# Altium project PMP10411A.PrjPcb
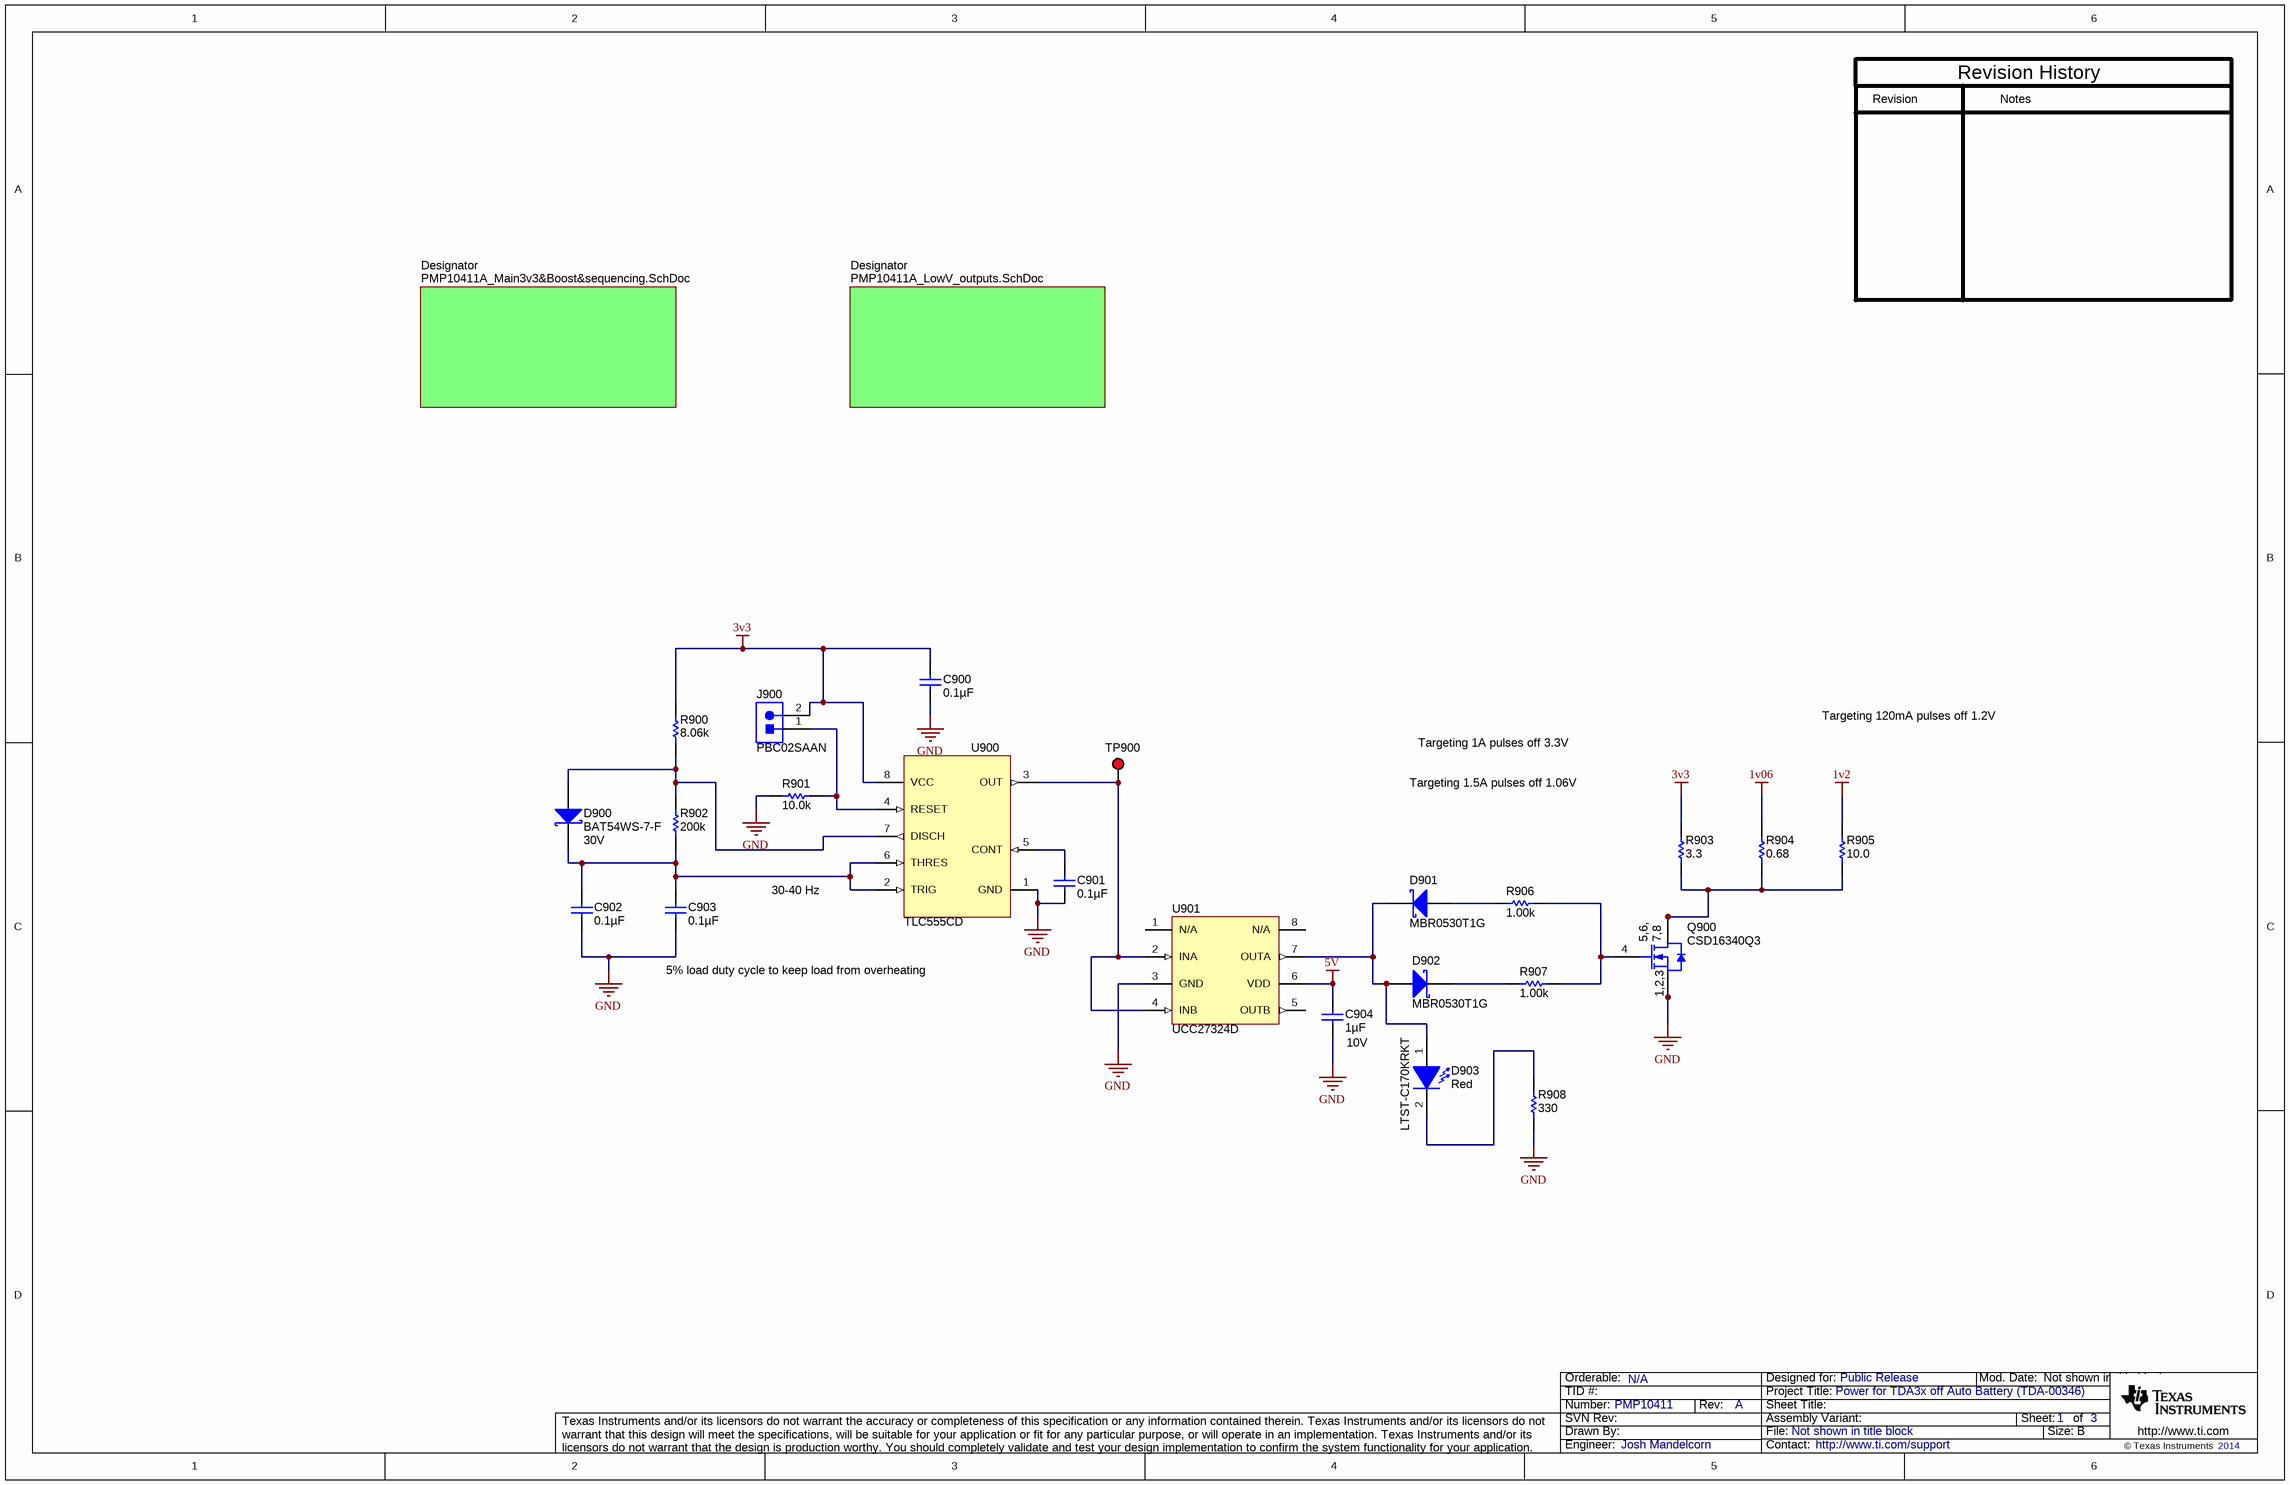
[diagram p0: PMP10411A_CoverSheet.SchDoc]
TechSupport: http://www.ti.com/support; SCH_Rev: A; PRJ_Title: Power for TDA3x off Auto Battery (TDA-00346); PRJ_Number: PMP10411; PRJ_Engineer: Josh Mandelcorn; PRJ_Customer: Public Release; PCB_Rev: A; PCB_Layout: Who did the Layout?; EVM_Orderable: N/A; CopyrightYear: 2014
3 sheets, 168 parts. Net scope: flat (ports and power ports of the same name join across sheets).
Board file: PMP10411A_TID.PcbDoc
Sheets:
  PMP10411A_CoverSheet.SchDoc
    Designator = PMP10411A_Main3v3&Boost&sequencing.SchDoc
    Designator = PMP10411A_LowV_outputs.SchDoc

## Sheet PMP10411A_CoverSheet.SchDoc
size 431 x 279 mm; Date: Not shown in title block; ApprovedBy: Not shown in title block; CheckedBy: Not shown in title block; Author: Not shown in title block; CompanyName: Not shown in title block; Engineer: Not shown in title block; Organization: Not shown in title block; Address1: Not shown in title block; Address2: Not shown in title block; Address3: Not shown in title block; Address4: Not shown in title block; DocumentNumber: 1; Revision: Use project parameter SCH_Rev; SheetNumber: 1; SheetTotal: 3; PageSetup: Record=PageOptions¦CenterHorizontal=True¦CenterVertical=True¦PrintScale=1.00¦XCorrection=1.00¦YCorrection=1.00¦PrintKind=0¦BorderSize=5000000¦LeftOffset=0¦BottomOffset=0¦Orientation=2¦PaperLength=1000¦PaperWidth=1000¦Scale=100¦PaperSource=15¦PrintQuality=600¦MediaType=1¦DitherType=10¦PaperKind=Letter¦PrintScaleMode=1

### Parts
C900  ValueDisplayed: 0.1µF  [0402]  (hidden comment: C1005X7R1H104M)
C901  ValueDisplayed: 0.1µF  [0402]  (hidden comment: C1005X7R1H104M)
C902  ValueDisplayed: 0.1µF  [0402]  (hidden comment: C1005X7R1H104M)
C903  ValueDisplayed: 0.1µF  [0402]  (hidden comment: C1005X7R1H104M)
C904  ValueDisplayed: 1µF  Value2: 10V  [0402]  (hidden comment: GRM155R61A105KE15D)
D900  BAT54WS-7-F  value 30V  [sod-323]
D901  MBR0530T1G  [SOD-123]
D902  MBR0530T1G  [SOD-123]
D903  LTST-C170KRKT  value Red  [LED_LTST-C170]
J900  PBC02SAAN  [Sullins_PBC02SAAN]
Q900  CSD16340Q3  [TRANS_NexFET_Q3]
R900  value 8.06k  [0402]  (hidden comment: CRCW04028K06FKED)
R901  value 10.0k  [0402]  (hidden comment: CRCW040210K0FKED)
R902  value 200k  [0402]  (hidden comment: CRCW0402200KFKED)
R903  ValueDisplayed: 3.3  [1210M]  (hidden comment: ERJ-P14J3R3U)
R904  ValueDisplayed: 0.68  [1206]  (hidden comment: ERJ-8RQFR68V)
R905  ValueDisplayed: 10.0  [1206]  (hidden comment: CRCW120610R0FKEA)
R906  ValueDisplayed: 1.00k  [0603]  (hidden comment: CRCW06031K00FKEA)
R907  ValueDisplayed: 1.00k  [0603]  (hidden comment: CRCW06031K00FKEA)
R908  value 330  [0402]  (hidden comment: CRCW0402330RJNED)
TP900  5000  [Keystone5000]  (value not drawn)
U900  TLC555CD  [D0008A_N]
U901  UCC27324D  [D0008A_N]

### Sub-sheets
Designator = PMP10411A_Main3v3&Boost&sequencing.SchDoc: no entries
Designator = PMP10411A_LowV_outputs.SchDoc: no entries

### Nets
1v2: R905.2
1v06: R904.2
3v3: C900.1 J900.2 R900.2 R903.2 U900.8(VCC)
5V: C904.1 U901.6(VDD)
GND: C900.2 C901.2 C902.2 C903.2 C904.2 Q900.1(S) Q900.2(S) Q900.3(S) R901.1 R908.1 U900.1(GND) U901.3(GND)
NetC901_1: C901.1 U900.5(CONT)
NetC902_1: C902.1 C903.1 D900.1(K) R902.1 U900.2(TRIG) U900.6(THRES)
NetD900_2: D900.2(A) R900.1 R902.2 U900.7(DISCH)
NetD901_1: D901.1(K) D902.2(A) D903.1(A) U901.7(OUTA)
NetD901_2: D901.2(A) R906.1
NetD902_1: D902.1(K) R907.1
NetD903_2: D903.2(K) R908.2
NetJ900_1: J900.1 R901.2 U900.4(RESET)
NetQ900_4: Q900.4(G) R906.2 R907.2
NetQ900_5: Q900.5(D) Q900.6(D) Q900.7(D) Q900.8(D) R903.1 R904.1 R905.1
NetTP900_1: TP900.1 U900.3(OUT) U901.2(INA) U901.4(INB)

Not connected (* = marked no-connect by the designer): U901 1(N/A) 5(OUTB) 8(N/A)

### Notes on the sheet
- Revision
- Notes
- Revision History
- Targeting 1A pulses off 3.3V
- Targeting 120mA pulses off 1.2V
- Targeting 1.5A pulses off 1.06V
- 30-40 Hz
- 5% load duty cycle to keep load from overheating

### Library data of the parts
C900-C903 = C1005X7R1H104M: CAP, CERM, 0.1uF, 50V, +/-20%, X7R, 0402; Manufacturer: TDK; Polarized: N; CompType: Capacitor; U/M: EA; Cap_F: 0.0000001; Tolerance_%: 20; Value1: Unknown; VDC_V: 50; TempCo: C0G/NP0; TaMin_C: -55; TaMax_C: 125
C904 = GRM155R61A105KE15D: CAP, CERM, 1uF, 10V, +/-10%, X5R, 0402; Manufacturer: MuRata; Polarized: N; CompType: Capacitor; U/M: EA; Cap_F: 0.000001; Tolerance_%: 10; Value1: Unknown; TaMin_C: -55; TaMax_C: 85
D900 = BAT54WS-7-F: Diode, Schottky, 30V, 0.2A, SOD-323; Manufacturer: Diodes Inc.; U/M: EA; Vf_V: 0.7; Value2: 0.7V; Io_A: 0.2; Vr_V: 30; TJmax_C: 125
D901 D902 = MBR0530T1G: Diode, Schottky, 30V, 0.5A, SOD-123; Manufacturer: ON Semiconductor; U/M: EA; Vf_V: 0.43; Value2: 0.43V; Io_A: 0.5; Vr_V: 30; TJmax_C: 125; RJC_CperW: 150
D903 = LTST-C170KRKT: LED, Red, SMD; Manufacturer: Lite-On; Type: AlInGaP; Vf_V: 2; Value2: 2V; Io_A: 20; Value1: W; U/M: EA
J900 = PBC02SAAN: Header, 100mil, 2x1, Gold, TH; Manufacturer: Sullins Connector Solutions; SymbolCreator: a0412235; U/M: EA
Q900 = CSD16340Q3: MOSFET, N-CH, 25 V, 60 A, SON 3.3x3.3mm; Manufacturer: Texas Instruments; Alternate Manufacturer: None; U/M: EA; ChType: N; Value: 25V; VdsMax_V: 25; Value1: 0.0043 ohm; Rdson45_ohm: 0.0043; Value2: 6.5 nC; QgTyp_nC: 6.5; Vgs_V: 10; IdsMax_A: 60
R900 = CRCW04028K06FKED: RES, 8.06k ohm, 1%, 0.063W, 0402; Manufacturer: Vishay-Dale; CompType: Resistor; Res_ohm: 8060; Value_Code: 8k06; Tolerance_%: 1; Power_W: 0.063; VDC_V: 50; TempCo: 100 ppm/C; EIA_Code: E96; U/M: EA
R901 = CRCW040210K0FKED: RES, 10.0k ohm, 1%, 0.063W, 0402; Manufacturer: Vishay-Dale; CompType: Resistor; Res_ohm: 10000; Value_Code: 10k0; Tolerance_%: 1; Power_W: 0.063; VDC_V: 50; TempCo: 100 ppm/C; EIA_Code: E96; U/M: EA
R902 = CRCW0402200KFKED: RES, 200k ohm, 1%, 0.063W, 0402; Manufacturer: Vishay-Dale; CompType: Resistor; Res_ohm: 200000; Tolerance_%: 1; Power_W: 0.063; VDC_V: 50; TempCo: 100 ppm/C; EIA_Code: E96; U/M: EA
R903 = ERJ-P14J3R3U: RES, 3.3, 5%, 0.5 W, 1210; Manufacturer: Panasonic; CompType: Resistor; Value: 3.3; Value_Code: 3R30; Tolerance_%: 5; Power_W: 0.5; Value2: 0.5W; VDC_V: 200; TempCo: 600 ppm/C; EIA_Code: E24; U/M: EA
R904 = ERJ-8RQFR68V: RES, 0.68, 1%, 0.25 W, 1206; Manufacturer: Panasonic; CompType: Resistor; Value: 0.68; Value_Code: R680; Tolerance_%: 1; Power_W: 0.25; Value2: 0.25W; TempCo: 250 ppm/C; EIA_Code: E96; U/M: EA
R905 = CRCW120610R0FKEA: RES, 10.0, 1%, 0.25 W, 1206; Manufacturer: Vishay-Dale; CompType: Resistor; Value: 10.0; Res_ohm: 10; Value_Code: 10R0; Tolerance_%: 1; Power_W: 0.25; Value2: 0.25W; VDC_V: 200; TempCo: 100 ppm/C; EIA_Code: E96; U/M: EA
R906 R907 = CRCW06031K00FKEA: RES, 1.00 k, 1%, 0.1 W, 0603; Manufacturer: Vishay-Dale; CompType: Resistor; Value: 1.00k; Res_ohm: 1000; Value_Code: 1k00; Tolerance_%: 1; Power_W: 0.1; Value2: 0.1W; VDC_V: 75; TempCo: 100 ppm/C; EIA_Code: E96; U/M: EA
R908 = CRCW0402330RJNED: RES, 330 ohm, 5%, 0.063W, 0402; Manufacturer: Vishay-Dale; CompType: Resistor; Value_Code: 330R; Tolerance_%: 5; Power_W: 0.063; VDC_V: 50; TempCo: 200 ppm/C; EIA_Code: E24; U/M: EA
TP900 = 5000: Test Point, Miniature, Red, TH; Manufacturer: Keystone; CompType: Test Point Loop; U/M: EA
U900 = TLC555CD: LinCMOS Timer, D0008A; Manufacturer: Texas Instruments; SymbolCreator: a0799628; CompType: IC; U/M: EA
U901 = UCC27324D: DUAL 4-A PEAK HIGH SPEED LOW- SIDE POWER MOSFET DRIVERS, D0008A; Manufacturer: Texas Instruments; SymbolCreator: a0412235; CompType: IC; U/M: EA

## Sheet PMP10411A_Main3v3&Boost&sequencing.SchDoc
size 431 x 279 mm; Date: Not shown in title block; ApprovedBy: Not shown in title block; CheckedBy: Not shown in title block; Author: Not shown in title block; CompanyName: Not shown in title block; Engineer: Not shown in title block; Organization: Not shown in title block; Address1: Not shown in title block; Address2: Not shown in title block; Address3: Not shown in title block; Address4: Not shown in title block; DocumentNumber: 2; Revision: Use project parameter SCH_Rev; SheetNumber: 2; SheetTotal: 3; PageSetup: Record=PageOptions¦CenterHorizontal=True¦CenterVertical=True¦PrintScale=1.00¦XCorrection=1.00¦YCorrection=1.00¦PrintKind=0¦BorderSize=5000000¦LeftOffset=0¦BottomOffset=0¦Orientation=2¦PaperLength=1000¦PaperWidth=1000¦Scale=100¦PaperSource=15¦PrintQuality=600¦MediaType=1¦DitherType=10¦PaperKind=Letter¦PrintScaleMode=1
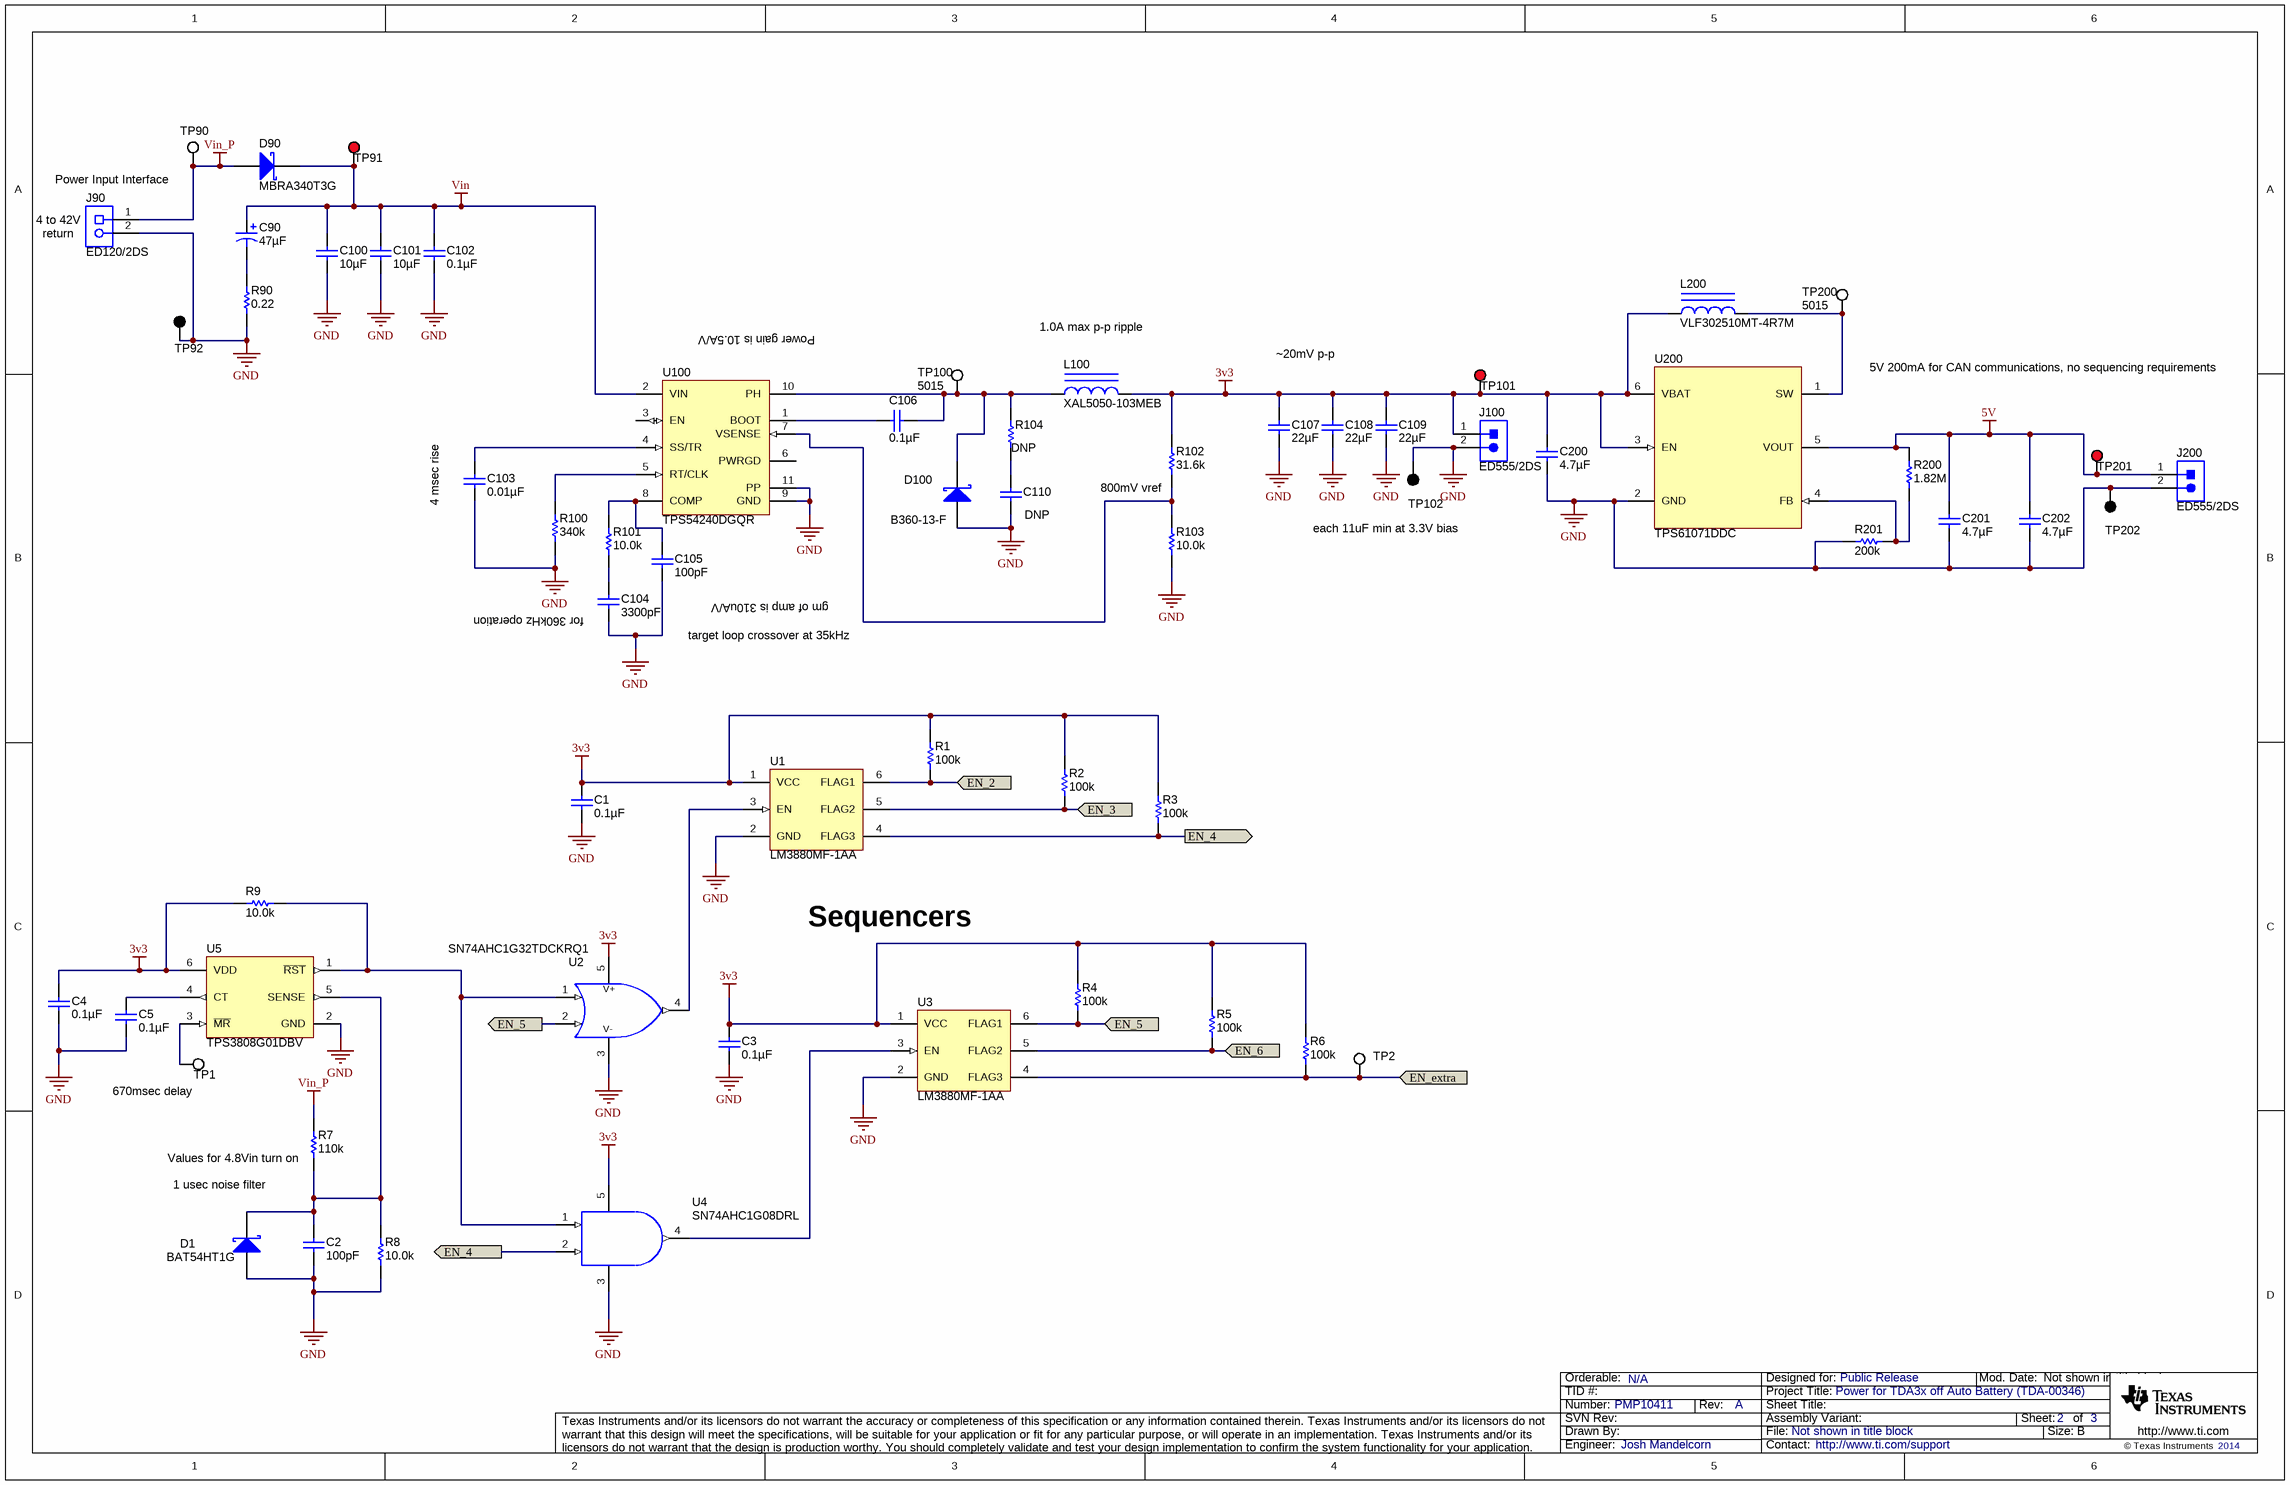
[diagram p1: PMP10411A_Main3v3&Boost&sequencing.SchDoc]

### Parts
C1  ValueDisplayed: 0.1µF  [0402]  (hidden comment: GRM155R61E104KA87D)
C2  ValueDisplayed: 100pF  [0402]  (hidden comment: GRM1535C1H101JDD5D)
C3  ValueDisplayed: 0.1µF  [0402]  (hidden comment: GRM155R61E104KA87D)
C4  ValueDisplayed: 0.1µF  [0402]  (hidden comment: GRM155R61E104KA87D)
C5  ValueDisplayed: 0.1µF  [0402]  (hidden comment: GRM155R61E104KA87D)
C90  ValueDisplayed: 47µF  [SM_RADIAL_6.3BMM]  (hidden comment: UUD1H470MCL1GS)
C100  ValueDisplayed: 10µF  [1210]  (hidden comment: GRM32ER71H106KA12L)
C101  ValueDisplayed: 10µF  [1210]  (hidden comment: GRM32ER71H106KA12L)
C102  ValueDisplayed: 0.1µF  [0603]  (hidden comment: 06035C104KAT2A)
C103  ValueDisplayed: 0.01µF  [0402]  (hidden comment: C1005X7R1E103K)
C104  ValueDisplayed: 3300pF  [0402]  (hidden comment: C1005X7R1H332K)
C105  ValueDisplayed: 100pF  [0402]  (hidden comment: GRM1535C1H101JDD5D)
C106  ValueDisplayed: 0.1µF  [0402]  (hidden comment: GRM155R61E104KA87D)
C107  ValueDisplayed: 22µF  [0805_HV]  (hidden comment: GRM21BR61A226ME44)
C108  ValueDisplayed: 22µF  [0805_HV]  (hidden comment: GRM21BR61A226ME44)
C109  ValueDisplayed: 22µF  [0805_HV]  (hidden comment: GRM21BR61A226ME44)
C110  DNP  [0603]  (value not drawn)
C200  ValueDisplayed: 4.7µF  [0603]  (hidden comment: CGB3B1X5R1A475K055AC)
C201  ValueDisplayed: 4.7µF  [0603]  (hidden comment: CGB3B1X5R1A475K055AC)
C202  ValueDisplayed: 4.7µF  [0603]  (hidden comment: CGB3B1X5R1A475K055AC)
D1  BAT54HT1G  [sod-323]
D90  MBRA340T3G  [SMA]
D100  B360-13-F  [SMC]
J90  ED120/2DS  [CONN_ED120-2DS]
J100  ED555/2DS  [TERM_BLK_ED555-2DS]
J200  ED555/2DS  [TERM_BLK_ED555-2DS]
L100  XAL5050-103MEB  [XAL5050]
L200  VLF302510MT-4R7M  [VLF302510]
R1  ValueDisplayed: 100k  [0402]  (hidden comment: CRCW0402100KFKED)
R2  ValueDisplayed: 100k  [0402]  (hidden comment: CRCW0402100KFKED)
R3  ValueDisplayed: 100k  [0402]  (hidden comment: CRCW0402100KFKED)
R4  ValueDisplayed: 100k  [0402]  (hidden comment: CRCW0402100KFKED)
R5  ValueDisplayed: 100k  [0402]  (hidden comment: CRCW0402100KFKED)
R6  ValueDisplayed: 100k  [0402]  (hidden comment: CRCW0402100KFKED)
R7  ValueDisplayed: 110k  [0402]  (hidden comment: CRCW0402110KFKED)
R8  ValueDisplayed: 10.0k  [0402]  (hidden comment: CRCW040210K0FKED)
R9  ValueDisplayed: 10.0k  [0402]  (hidden comment: CRCW040210K0FKED)
R90  ValueDisplayed: 0.22  [0603]  (hidden comment: ERJ-3RQFR22V)
R100  ValueDisplayed: 340k  [0402]  (hidden comment: CRCW0402340KFKED)
R101  ValueDisplayed: 10.0k  [0402]  (hidden comment: CRCW040210K0FKED)
R102  ValueDisplayed: 31.6k  [0402]  (hidden comment: CRCW040231K6FKED)
R103  ValueDisplayed: 10.0k  [0402]  (hidden comment: CRCW040210K0FKED)
R104  DNP  [0805_HV]  (value not drawn)
R200  ValueDisplayed: 1.82M  [0402]  (hidden comment: CRCW04021M82FKED)
R201  ValueDisplayed: 200k  [0402]  (hidden comment: CRCW0402200KFKED)
TP1  5002  [Keystone5002]  (value not drawn)
TP2  5002  [Keystone5002]  (value not drawn)
TP90  5002  [Keystone5002]  (value not drawn)
TP91  5000  [Keystone5000]  (value not drawn)
TP92  5001  [Keystone5001]  (value not drawn)
TP100  5015  [Testpoint_Keystone_Miniature]
TP101  5000  [Keystone5000]  (value not drawn)
TP102  5001  [Keystone5001]  (value not drawn)
TP200  5015  [Testpoint_Keystone_Miniature]
TP201  5000  [Keystone5000]  (value not drawn)
TP202  5001  [Keystone5001]  (value not drawn)
U1  LM3880MF-1AA  [MF06A_N]
U2  SN74AHC1G32TDCKRQ1  [DCK0005A_N]
U3  LM3880MF-1AA  [MF06A_N]
U4  SN74AHC1G08DRL  [DRL0005A]
U5  TPS3808G01DBV  [DBV0006A_N]
U100  TPS54240DGQR  [DGQ0010D_N]
U200  TPS61071DDC  [DDC0006A_N]

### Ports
EN_2, EN_3, EN_4, EN_4 (out), EN_5, EN_5 (out), EN_6, EN_extra

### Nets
3v3: C1.2 C3.2 C4.2 C107.1 C108.1 C109.1 C200.1 J100.1 L100.2 L200.1 R1.2 R2.2 R3.2 R4.2 R5.2 R6.2 R9.2 R102.2 TP101.1 U1.1(VCC) U2.5(VCC) U3.1(VCC) U4.5(VCC) U5.6(VDD) U200.3(EN) U200.6(VBAT)
5V: C201.1 C202.1 J200.1 R200.2 TP201.1 U200.5(VOUT)
GND: C1.1 C2.1 C3.1 C4.1 C5.1 C100.2 C101.2 C102.2 C103.1 C104.1 C105.1 C107.2 C108.2 C109.2 C110.2 C200.2 C201.2 C202.2 D1.2(A) D100.2(A) J90.2 J100.2 J200.2 R8.1 R90.1 R100.1 R103.1 R201.1 TP92.1 TP102.1 TP202.1 U1.2(GND) U2.3(GND) U3.2(GND) U4.3(GND) U5.2(GND) U100.9(GND) U100.11(PP) U200.2(GND)
Vin: C90.1(+) C100.1 C101.1 C102.1 D90.1(K) TP91.1 U100.2(VIN)
Vin_P: D90.2(A) J90.1 R7.2 TP90.1
EN_2: R1.1 U1.6(FLAG1) ; port EN_2
EN_3: R2.1 U1.5(FLAG2) ; port EN_3
EN_4: R3.1 U1.4(FLAG3) U4.2(B) ; port EN_4
EN_5: R4.1 U2.2(B) U3.6(FLAG1) ; port EN_5
EN_6: R5.1 U3.5(FLAG2) ; port EN_6
EN_extra: R6.1 TP2.1 U3.4(FLAG3) ; port EN_extra
NetC2_2: C2.2 D1.1(K) R7.1 R8.2 U5.5(SENSE)
NetC5_2: C5.2 U5.4(CT)
NetC90_2: C90.2(-) R90.2
NetC103_2: C103.2 U100.4(SS/TR)
NetC104_2: C104.2 R101.1
NetC105_2: C105.2 R101.2 U100.8(COMP)
NetC106_1: C106.1 D100.1(K) L100.1 R104.2 TP100.1 U100.10(PH)
NetC106_2: C106.2 U100.1(BOOT)
NetC110_1: C110.1 R104.1
NetL200_2: L200.2 TP200.1 U200.1(SW)
NetR9_1: R9.1 U2.1(A) U4.1(A) U5.1(~{RST})
NetR100_2: R100.2 U100.5(RT/CLK)
NetR102_1: R102.1 R103.2 U100.7(VSENSE)
NetR200_1: R200.1 R201.2 U200.4(FB)
NetTP1_1: TP1.1 U5.3(~{MR})
NetU1_3: U1.3(EN) U2.4(Y)
NetU3_3: U3.3(EN) U4.4(Y)

Not connected (* = marked no-connect by the designer): U100 3(EN) 6(PWRGD)

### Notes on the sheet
- (near J90) return
- (near J90) 4 to 42V
- Power Input Interface
- (near U100) Power gain is 10.5A/V
- 1.0A max p-p ripple
- |0mV p-p
- 5V 200mA for CAN communications, no sequencing requirements
- (near C103) 4 msec rise
- (near R104) DNP
- (near R102) 800mV vref
- (near C110) DNP
- (near TP102) each 11uF min at 3.3V bias
- (near C104) for 360kHz operation
- gm of amp is 310uA/V
- target loop crossover at 35kHz
- Sequencers
- (near TP1) 670msec delay
- (near R7) Values for 4.8Vin turn on
- 1 usec noise filter

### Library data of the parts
C1 C3-C5 C106 = GRM155R61E104KA87D: CAP, CERM, 0.1 µF, 25 V, +/- 10%, X5R, 0402; Manufacturer: MuRata; Polarized: N; CompType: Capacitor; Value: 0.1uF; U/M: EA; Cap_F: 0.0000001; Tolerance_%: 10; Value1: Unknown; VDC_V: 25; Value2: 25V; TaMin_C: -55; TaMax_C: 85
C2 C105 = GRM1535C1H101JDD5D: CAP, CERM, 100 pF, 50 V, +/- 5%, C0G/NP0, 0402; Manufacturer: MuRata; Polarized: N; CompType: Capacitor; Value: 100pF; U/M: EA; Cap_F: 0.0000000001; Tolerance_%: 5; Value1: Unknown; VDC_V: 50; Value2: 50V; TaMin_C: -55; TaMax_C: 125
C90 = UUD1H470MCL1GS: CAP, AL, 47 µF, 50 V, +/- 20%, 0.68 ohm, SMD; Manufacturer: Nichicon; Polarized: Y; CompType: Capacitor; Value: 47uF; U/M: EA; Cap_F: 0.000047; Tolerance_%: 20; VDC_V: 50; Value2: 50V; ESR_ohm: 0.68; IRMS_A: 0.185; TaMin_C: -55; TaMax_C: 105; Cap_Case: 6.3x7.7
C100 C101 = GRM32ER71H106KA12L: CAP, CERM, 10uF, 50V, +/-10%, X7R, 1210; Manufacturer: MuRata; Polarized: N; CompType: Capacitor; U/M: EA; Cap_F: 0.00001; Tolerance_%: 10; Value1: Unknown; VDC_V: 50; TaMin_C: -55; TaMax_C: 125
C102 = 06035C104KAT2A: CAP, CERM, 0.1uF, 50V, +/-10%, X7R, 0603; Manufacturer: AVX; Polarized: N; CompType: Capacitor; U/M: EA; Cap_F: 0.0000001; Tolerance_%: 10; Value1: Unknown; VDC_V: 50; TaMin_C: -55; TaMax_C: 125
C103 = C1005X7R1E103K: CAP, CERM, 0.01 µF, 25 V, +/- 10%, X7R, 0402; Manufacturer: TDK; Polarized: N; CompType: Capacitor; Value: 0.01uF; U/M: EA; Cap_F: 0.00000001; Tolerance_%: 10; ESR_ohm: 0.0623; Value1: 0.0623 ohm; VDC_V: 25; Value2: 25V; TaMin_C: -55; TaMax_C: 125
C104 = C1005X7R1H332K: CAP, CERM, 3300 pF, 50 V, +/- 10%, X7R, 0402; Manufacturer: TDK; Polarized: N; CompType: Capacitor; Value: 3300pF; U/M: EA; Cap_F: 0.0000000033; Tolerance_%: 10; ESR_ohm: 0.12; Value1: 0.12 ohm; VDC_V: 50; Value2: 50V; TaMin_C: -55; TaMax_C: 125
C107-C109 = GRM21BR61A226ME44: CAP, CERM, 22 µF, 10 V, +/- 20%, X5R, 0805; Manufacturer: MuRata; Polarized: N; CompType: Capacitor; Value: 22uF; U/M: EA; Cap_F: 0.000022; Tolerance_%: 20; Value1: Unknown; VDC_V: 10; Value2: 10V; TaMin_C: -55; TaMax_C: 85; Cap_Case: 0805
C110 = 06035A471JAT2A: CAP, CERM, 470pF, 50V, +/-5%, C0G/NP0, 0603; Manufacturer: AVX; Polarized: N; CompType: Capacitor; U/M: EA; Cap_F: 0.00000000047; Tolerance_%: 5; ESR_Ohm: 0.063; Value1: 0.063 ohm; VDC_V: 50; TaMin_C: -55; TaMax_C: 125
C200-C202 = CGB3B1X5R1A475K055AC: CAP, CERM, 4.7 µF, 10 V, +/- 10%, X5R, 0603; Manufacturer: TDK; Polarized: N; CompType: Capacitor; Value: 4.7uF; U/M: EA; Cap_F: 0.0000047; Tolerance_%: 10; Value1: Unknown; Value2: 10V; TaMin_C: -55; TaMax_C: 85
D1 = BAT54HT1G: Diode, Schottky, 30 V, 0.2 A, SOD-323; Manufacturer: ON Semiconductor; U/M: EA; Vf_V: 0.35; Value: 30V; Value1: 0.2A; Value2: 0.35V; Io_A: 0.2; Vr_V: 30
D90 = MBRA340T3G: Diode, Schottky, 40 V, 3 A, SMA; Manufacturer: ON Semiconductor; U/M: EA; Vf_V: 0.415; Value: 40V; Value1: 3A; Value2: 0.415V; Io_A: 3; Vr_V: 40; RJC_CperW: 15
D100 = B360-13-F: Diode, Schottky, 60 V, 3 A, SMC; Manufacturer: Diodes Inc.; U/M: EA; Vf_V: 0.7; Value: 60V; Value1: 3A; Value2: 0.7V; Io_A: 3; Vr_V: 60; TJmax_C: 125; RJC_CperW: 20
J90 = ED120/2DS: TERMINAL BLOCK 5.08MM VERT 2POS, TH; Manufacturer: On-Shore Technology; SymbolCreator: a0412235; U/M: EA
J100 J200 = ED555/2DS: Terminal Block, 6A, 3.5mm Pitch, 2-Pos, TH; Manufacturer: On-Shore Technology; SymbolCreator: a0412235; CompType: Connector; U/M: EA
L100 = XAL5050-103MEB: Inductor, Shielded, Composite, 10 µH, 4.9 A, 0.05 ohm, SMD; Manufacturer: Coilcraft; Value: 10uH; Ind_H: 10.0E-6; ValueDisplayed: 10µH; Imax_A: 4.9; Irms: 4.9A @ 40C rise; Isat: 4.9A @ 30% inductance drop; DCR_ohm: 0.05; Value2: 4.9A
L200 = VLF302510MT-4R7M: Inductor, Shielded, Ferrite, 4.7 µH, 0.86 A, 0.168 ohm, SMD; Manufacturer: TDK; Value: 4.7uH; Ind_H: 4.7E-6; ValueDisplayed: 4.7µH; Imax_A: 0.86; Irms: 1.08A @ 40C rise; Isat: 0.86A @ 30% inductance drop; DCR_ohm: 0.168; Value2: 0.86A
R1-R6 = CRCW0402100KFKED: RES, 100 k, 1%, 0.063 W, 0402; Manufacturer: Vishay-Dale; CompType: Resistor; Value: 100k; Res_ohm: 100000; Tolerance_%: 1; Power_W: 0.063; Value2: 0.063W; VDC_V: 50; TempCo: 100 ppm/C; EIA_Code: E96; U/M: EA
R7 = CRCW0402110KFKED: RES, 110 k, 1%, 0.063 W, 0402; Manufacturer: Vishay-Dale; CompType: Resistor; Value: 110k; Res_ohm: 110000; Tolerance_%: 1; Power_W: 0.063; Value2: 0.063W; VDC_V: 50; TempCo: 100 ppm/C; EIA_Code: E96; U/M: EA
R8 R9 R101 R103 = CRCW040210K0FKED: RES, 10.0 k, 1%, 0.063 W, 0402; Manufacturer: Vishay-Dale; CompType: Resistor; Value: 10.0k; Res_ohm: 10000; Value_Code: 10k0; Tolerance_%: 1; Power_W: 0.063; Value2: 0.063W; VDC_V: 50; TempCo: 100 ppm/C; EIA_Code: E96; U/M: EA
R90 = ERJ-3RQFR22V: RES, 0.22, 1%, 0.1 W, 0603; Manufacturer: Panasonic; CompType: Resistor; Value: 0.22; Value_Code: R220; Tolerance_%: 1; Power_W: 0.1; Value2: 0.1W; TempCo: 300 ppm/C; EIA_Code: E96; U/M: EA
R100 = CRCW0402340KFKED: RES, 340 k, 1%, 0.063 W, 0402; Manufacturer: Vishay-Dale; CompType: Resistor; Value: 340k; Res_ohm: 340000; Tolerance_%: 1; Power_W: 0.063; Value2: 0.063W; VDC_V: 50; TempCo: 100 ppm/C; EIA_Code: E96; U/M: EA
R102 = CRCW040231K6FKED: RES, 31.6 k, 1%, 0.063 W, 0402; Manufacturer: Vishay-Dale; CompType: Resistor; Value: 31.6k; Res_ohm: 31600; Value_Code: 31k6; Tolerance_%: 1; Power_W: 0.063; Value2: 0.063W; VDC_V: 50; TempCo: 100 ppm/C; EIA_Code: E96; U/M: EA
R104 = CRCW08058R06FKEA: RES, 8.06 ohm, 1%, 0.125W, 0805; Manufacturer: Vishay-Dale; CompType: Resistor; Value: 8.06; Value_Code: 8R06; Tolerance_%: 1; Power_W: 0.125; VDC_V: 150; TempCo: 100 ppm/C; EIA_Code: E96; U/M: EA
R200 = CRCW04021M82FKED: RES, 1.82 M, 1%, 0.063 W, 0402; Manufacturer: Vishay-Dale; CompType: Resistor; Value: 1.82Meg; Res_ohm: 1820000; Value_Code: 1M82; Tolerance_%: 1; Power_W: 0.063; Value2: 0.063W; VDC_V: 50; TempCo: 100 ppm/C; EIA_Code: E96; U/M: EA
R201 = CRCW0402200KFKED: RES, 200 k, 1%, 0.063 W, 0402; Manufacturer: Vishay-Dale; CompType: Resistor; Value: 200k; Res_ohm: 200000; Tolerance_%: 1; Power_W: 0.063; Value2: 0.063W; VDC_V: 50; TempCo: 100 ppm/C; EIA_Code: E96; U/M: EA
TP1 TP2 TP90 = 5002: Test Point, Miniature, White, TH; Manufacturer: Keystone; CompType: Test Point Loop; U/M: EA
TP91 TP101 TP201 = 5000: as TP900 on sheet PMP10411A_CoverSheet
TP92 TP102 TP202 = 5001: Test Point, Miniature, Black, TH; Manufacturer: Keystone; CompType: Test Point Loop; U/M: EA
TP100 TP200 = 5015: Test Point, Miniature, SMT; Manufacturer: Keystone; CompType: Test Point Loop; U/M: EA
U1 U3 = LM3880MF-1AA: Power Sequencer, 6-pin SOT-23; Manufacturer: National Semiconductor; PackageTopMarking: F20A*XTT; PowerWise: N; CompType: MiscPower
U2 = SN74AHC1G32TDCKRQ1: Single 2-Input Positive-OR Gate, DCK0005A; Manufacturer: Texas Instruments; SymbolCreator: a0411947; CompType: IC; U/M: EA
U4 = SN74AHC1G08DRL: Single 2-Input Positive-AND Gate, DRL0005A; Alternate Manufacturer: None; Manufacturer: Texas Instruments; SymbolCreator: x0208326; CompType: IC; U/M: EA
U5 = TPS3808G01DBV: Low Quiescent Current, Programmable-Delay Supervisory Circuit, DBV0006A; Manufacturer: Texas Instruments; SymbolCreator: a0799628; CompType: IC; U/M: EA
U100 = TPS54240DGQR: Buck Inverting Buck-Boost Step Down Regulator with 3.5 to 42 V Input and 0.8 to 39 V Output, -40 to 150 degC, 10-Pin MSOP-PowerPAD (DGQ), Green (RoHS & no Sb/Br); Manufacturer: Texas Instruments; Alternate Manufacturer: None; Alternate PartNumber: Equivalent; Duty Cycle(Max)(%): 98; Iout(Max)(A): 2.5; Iq(Typ)(mA): 0.138; Rating: Catalog; Regulated Outputs(#): 1; SubFamily: Step-Down Regulator; Switch Current Limit(Typ)(A): 3.5; Topology: Buck, Inverting Buck-Boost; Vin(Max)(V): 42; Vout(Max)(V): 39; Vout(Min)(V): 0.8
U200 = TPS61071DDC: 90% Efficient Synchronous Boost Converter with 600-mA Switch, DDC0006A; Alternate Manufacturer: None; Manufacturer: Texas Instruments; SymbolCreator: a0411947; CompType: IC; U/M: EA

## Sheet PMP10411A_LowV_outputs.SchDoc
size 431 x 279 mm; Date: Not shown in title block; ApprovedBy: Not shown in title block; CheckedBy: Not shown in title block; Author: Not shown in title block; CompanyName: Not shown in title block; Engineer: Not shown in title block; Organization: Not shown in title block; Address1: Not shown in title block; Address2: Not shown in title block; Address3: Not shown in title block; Address4: Not shown in title block; DocumentNumber: 3; Revision: Use project parameter SCH_Rev; SheetNumber: 3; SheetTotal: 3; PageSetup: Record=PageOptions¦CenterHorizontal=True¦CenterVertical=True¦PrintScale=1.00¦XCorrection=1.00¦YCorrection=1.00¦PrintKind=0¦BorderSize=5000000¦LeftOffset=0¦BottomOffset=0¦Orientation=2¦PaperLength=1000¦PaperWidth=1000¦Scale=100¦PaperSource=15¦PrintQuality=600¦MediaType=1¦DitherType=10¦PaperKind=Letter¦PrintScaleMode=1
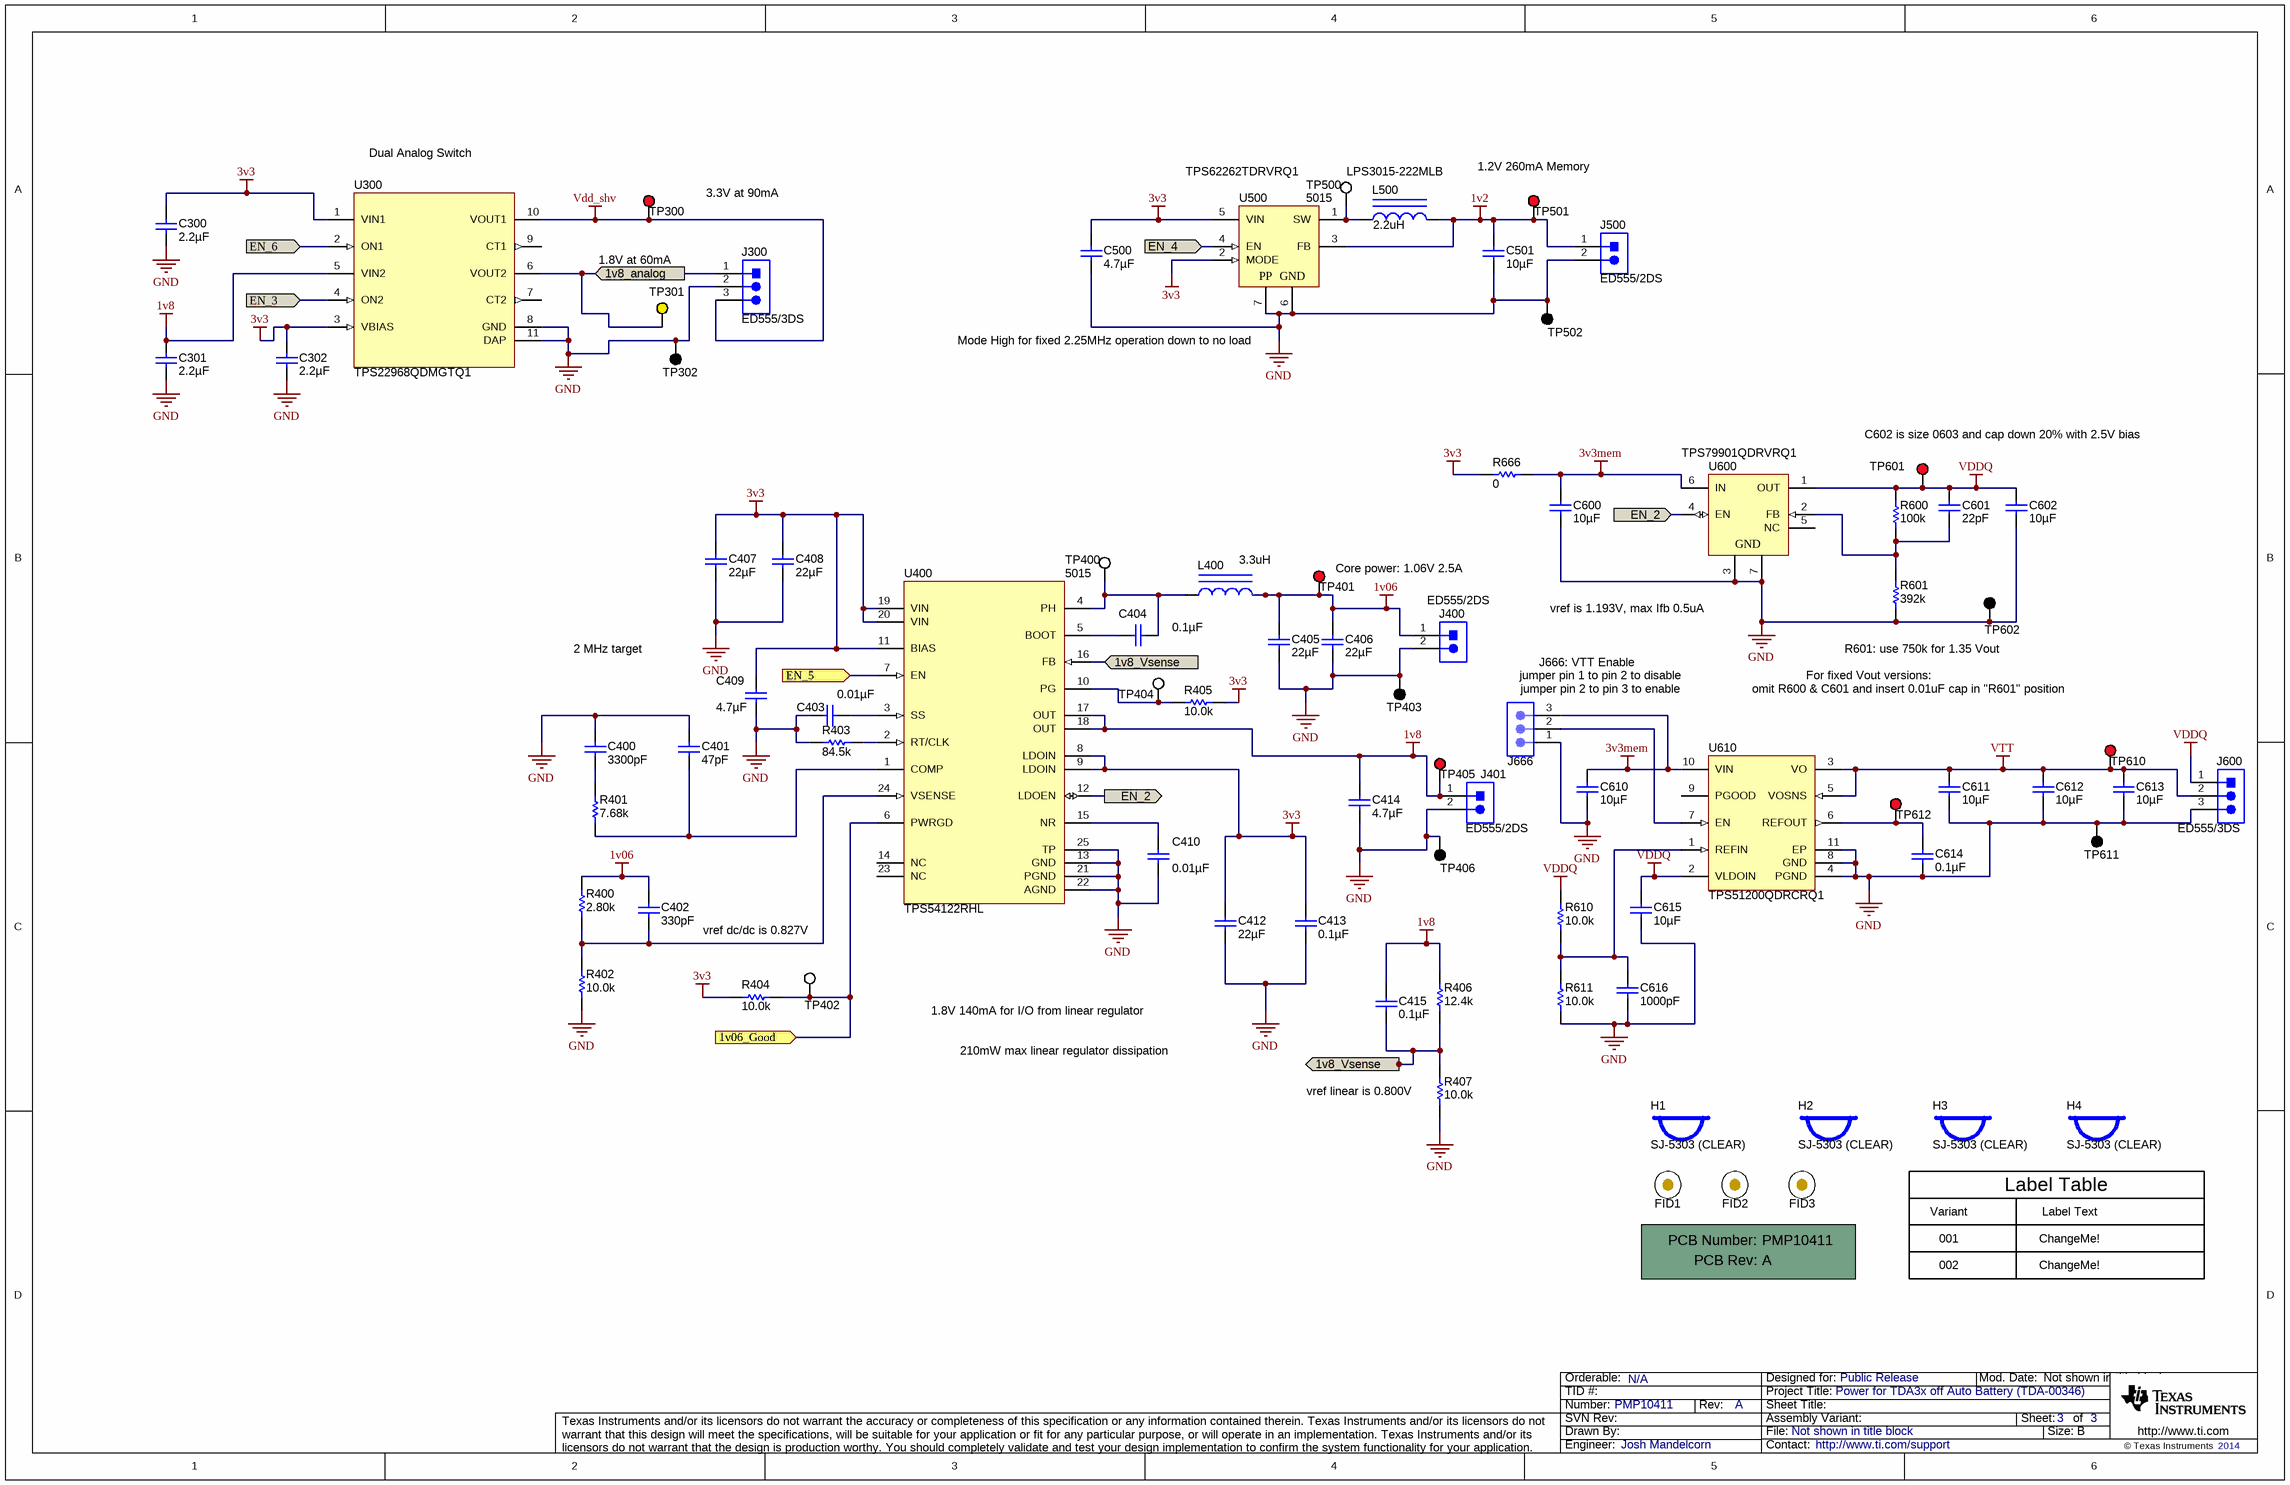
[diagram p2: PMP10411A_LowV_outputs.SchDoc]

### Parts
!PCB1  Printed Circuit Board  (value not drawn)  (mechanical)
C300  ValueDisplayed: 2.2µF  [0402]  (hidden comment: GRM155R60J225ME15D)
C301  ValueDisplayed: 2.2µF  [0402]  (hidden comment: GRM155R60J225ME15D)
C302  ValueDisplayed: 2.2µF  [0402]  (hidden comment: GRM155R60J225ME15D)
C400  ValueDisplayed: 3300pF  [0402]  (hidden comment: GRM155R71H332KA01D)
C401  ValueDisplayed: 47pF  [0402]  (hidden comment: GRM1555C1E470JA01D)
C402  ValueDisplayed: 330pF  [0402]  (hidden comment: GRM155R71H331KA01D)
C403  ValueDisplayed: 0.01µF  [0402]  (hidden comment: GRM155R71H103KA88D)
C404  ValueDisplayed: 0.1µF  [0402]  (hidden comment: GRM155R61E104KA87D)
C405  ValueDisplayed: 22µF  [0805_HV]  (hidden comment: GRM21BR61A226ME44)
C406  ValueDisplayed: 22µF  [0805_HV]  (hidden comment: GRM21BR61A226ME44)
C407  ValueDisplayed: 22µF  [0805_HV]  (hidden comment: GRM21BR61A226ME44)
C408  ValueDisplayed: 22µF  [0805_HV]  (hidden comment: GRM21BR61A226ME44)
C409  ValueDisplayed: 4.7µF  [0603]  (hidden comment: CGB3B1X5R1A475K055AC)
C410  ValueDisplayed: 0.01µF  [0402]  (hidden comment: GRM155R71H103KA88D)
C412  ValueDisplayed: 22µF  [0805_HV]  (hidden comment: GRM21BR61A226ME44)
C413  ValueDisplayed: 0.1µF  [0402]  (hidden comment: GRM155R61E104KA87D)
C414  ValueDisplayed: 4.7µF  [0603]  (hidden comment: GRM188R60J475ME19D)
C415  ValueDisplayed: 0.1µF  [0402]  (hidden comment: GRM155R61E104KA87D)
C500  ValueDisplayed: 4.7µF  [0603]  (hidden comment: GRM188R60J475ME19D)
C501  ValueDisplayed: 10µF  [0603]  (hidden comment: GRM188R60J106ME84)
C600  ValueDisplayed: 10µF  [0603]  (hidden comment: GRM188R60J106ME84)
C601  ValueDisplayed: 22pF  [0402]  (hidden comment: GRM1555C1H220JA01D)
C602  ValueDisplayed: 10µF  [0603]  (hidden comment: GRM188R60J106ME84)
C610  ValueDisplayed: 10µF  [0603]  (hidden comment: GRM188R60J106ME84)
C611  ValueDisplayed: 10µF  [0603]  (hidden comment: GRM188R60J106ME84)
C612  ValueDisplayed: 10µF  [0603]  (hidden comment: GRM188R60J106ME84)
C613  ValueDisplayed: 10µF  [0603]  (hidden comment: GRM188R60J106ME84)
C614  ValueDisplayed: 0.1µF  [0402]  (hidden comment: GRM155R61E104KA87D)
C615  ValueDisplayed: 10µF  [0603]  (hidden comment: GRM188R60J106ME84)
C616  ValueDisplayed: 1000pF  [0402]  (hidden comment: GRM155R61C102KA01D)
FID1  Fiducial  [Fiducial10-20]  (value not drawn)
FID2  Fiducial  [Fiducial10-20]  (value not drawn)
FID3  Fiducial  [Fiducial10-20]  (value not drawn)
H1  SJ-5303 (CLEAR)  [Bumpon_SJ5003Transparent]
H2  SJ-5303 (CLEAR)  [Bumpon_SJ5003Transparent]
H3  SJ-5303 (CLEAR)  [Bumpon_SJ5003Transparent]
H4  SJ-5303 (CLEAR)  [Bumpon_SJ5003Transparent]
J300  ED555/3DS  [TERM_BLK_ED555-3DS]
J400  ED555/2DS  [TERM_BLK_ED555-2DS]
J401  ED555/2DS  [TERM_BLK_ED555-2DS]
J500  ED555/2DS  [TERM_BLK_ED555-2DS]
J600  ED555/3DS  [TERM_BLK_ED555-3DS]
J666  PBC03SAAN  [PBC03SAAN]  (value not drawn)
L400  value 3.3uH  [XAL4030]  (hidden comment: XAL4030-332MEB)
L500  LPS3015-222MLB  value 2.2uH  [LPS3015]
R400  ValueDisplayed: 2.80k  [0402]  (hidden comment: CRCW04022K80FKED)
R401  value 7.68k  [0402]  (hidden comment: CRCW04027K68FKED)
R402  ValueDisplayed: 10.0k  [0402]  (hidden comment: CRCW040210K0FKED)
R403  ValueDisplayed: 84.5k  [0402]  (hidden comment: CRCW040284K5FKED)
R404  ValueDisplayed: 10.0k  [0402]  (hidden comment: CRCW040210K0FKED)
R405  ValueDisplayed: 10.0k  [0402]  (hidden comment: CRCW040210K0FKED)
R406  ValueDisplayed: 12.4k  [0402]  (hidden comment: CRCW040212K4FKED)
R407  ValueDisplayed: 10.0k  [0402]  (hidden comment: CRCW040210K0FKED)
R600  ValueDisplayed: 100k  [0402]  (hidden comment: CRCW0402100KFKED)
R601  ValueDisplayed: 392k  [0402]  (hidden comment: CRCW0402392KFKED)
R610  ValueDisplayed: 10.0k  [0402]  (hidden comment: CRCW040210K0FKED)
R611  ValueDisplayed: 10.0k  [0402]  (hidden comment: CRCW040210K0FKED)
R666  ValueDisplayed: 0  [0603]  (hidden comment: CRCW06030000Z0EA)
TP300  5000  [Keystone5000]  (value not drawn)
TP301  5004  [Keystone5004]  (value not drawn)
TP302  5001  [Keystone5001]  (value not drawn)
TP400  5015  [Testpoint_Keystone_Miniature]
TP401  5000  [Keystone5000]  (value not drawn)
TP402  5002  [Keystone5002]  (value not drawn)
TP403  5001  [Keystone5001]  (value not drawn)
TP404  5002  [Keystone5002]  (value not drawn)
TP405  5000  [Keystone5000]  (value not drawn)
TP406  5001  [Keystone5001]  (value not drawn)
TP500  5015  [Testpoint_Keystone_Miniature]
TP501  5000  [Keystone5000]  (value not drawn)
TP502  5001  [Keystone5001]  (value not drawn)
TP601  5000  [Keystone5000]  (value not drawn)
TP602  5001  [Keystone5001]  (value not drawn)
TP610  5000  [Keystone5000]  (value not drawn)
TP611  5001  [Keystone5001]  (value not drawn)
TP612  5000  [Keystone5000]  (value not drawn)
U300  TPS22968QDMGTQ1  [DMG0010A]
U400  TPS54122RHL  [RHL0024A]
U500  TPS62262TDRVRQ1  [DRV0006A]
U600  TPS79901QDRVRQ1  [DRV0006A]
U610  TPS51200QDRCRQ1  [DRC0010A]

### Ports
1v06_Good, 1v8_analog, 1v8_Vsense, EN_2, EN_3 (in), EN_4 (in), EN_5, EN_6 (in)

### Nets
1v2: C501.1 J500.1 L500.2 TP501.1 U500.3(FB)
1v06: C402.1 C405.1 C406.1 J400.1 L400.2 R400.1 TP401.1
1v8: C301.1 C414.1 C415.2 J401.1 R406.2 TP405.1 U300.5(VIN2) U400.17(OUT) U400.18(OUT)
3v3: C300.1 C302.1 C407.1 C408.1 C409.1 C412.1 C413.2 C500.1 R404.1 R405.2 R666.1 U300.1(VIN1) U300.3(VBIAS) U400.8(LDOIN) U400.9(LDOIN) U400.11(BIAS) U400.19(VIN) U400.20(VIN) U500.2(MODE) U500.5(VIN)
3v3mem: C600.1 C610.1 J666.3 R666.2 U600.6(IN) U610.10(VIN)
GND: C300.2 C301.2 C302.2 C400.1 C401.1 C403.1 C405.2 C406.2 C407.2 C408.2 C409.2 C410.1 C412.2 C413.1 C414.2 C500.2 C501.2 C600.2 C602.2 C610.2 C611.2 C612.2 C613.2 C614.1 C615.2 C616.2 J300.2 J400.2 J401.2 J500.2 J600.3 J666.1 R402.2 R403.1 R407.1 R601.1 R611.1 TP302.1 TP403.1 TP406.1 TP502.1 TP602.1 TP611.1 U300.8(GND) U300.11(DAP) U400.13(GND) U400.21(PGND) U400.22(AGND) U400.25(TP) U500.6(GND) U500.7(PP) U600.3(GND) U600.7(GND) U610.4(PGND) U610.8(GND) U610.11(EP)
Vdd_shv: J300.3 TP300.1 U300.10(VOUT1)
VDDQ: C601.1 C602.1 C615.1 J600.1 R600.2 R610.2 TP601.1 U600.1(OUT) U610.2(VLDOIN)
VTT: C611.1 C612.1 C613.1 J600.2 TP610.1 U610.3(VO) U610.5(VOSNS)
1v06_Good: R404.2 TP402.1 U400.6(PWRGD) ; port 1v06_Good
1v8_analog: J300.1 TP301.1 U300.6(VOUT2) ; port 1v8_analog
1v8_Vsense: C415.1 R406.1 R407.2 U400.16(FB) ; port 1v8_Vsense
EN_2: U400.12(LDOEN) U600.4(EN) ; port EN_2
EN_3: U300.4(ON2) ; port EN_3
EN_4: U500.4(EN) ; port EN_4
EN_5: U400.7(EN) ; port EN_5
EN_6: U300.2(ON1) ; port EN_6
NetC400_2: C400.2 R401.2
NetC401_2: C401.2 R401.1 U400.1(COMP)
NetC402_2: C402.2 R400.2 R402.1 U400.24(VSENSE)
NetC403_2: C403.2 U400.3(SS)
NetC404_1: C404.1 U400.5(BOOT)
NetC404_2: C404.2 L400.1 TP400.1 U400.4(PH)
NetC410_2: C410.2 U400.15(NR)
NetC601_2: C601.2 R600.1 R601.2 U600.2(FB)
NetC614_2: C614.2 TP612.1 U610.6(REFOUT)
NetC616_1: C616.1 R610.1 R611.2 U610.1(REFIN)
NetJ666_2: J666.2 U610.7(EN)
NetL500_1: L500.1 TP500.1 U500.1(SW)
NetR403_2: R403.2 U400.2(RT/CLK)
NetR405_1: R405.1 TP404.1 U400.10(PG)

Not connected (* = marked no-connect by the designer): U300 7(CT2) 9(CT1); U400 14(NC) 23(NC); U600 5(NC); U610 9(PGOOD)

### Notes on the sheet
- Dual Analog Switch
- (near TP501) 1.2V 260mA Memory
- 3.3V at 90mA
- 1.8V at 60mA
- Mode High for fixed 2.25MHz operation down to no load
- (near TP601) C602 is size 0603 and cap down 20% with 2.5V bias
- (near TP401) Core power: 1.06V 2.5A
- (near U600) vref is 1.193V, max Ifb 0.5uA
- 2 MHz target
- (near J666) J666: VTT Enable
- (near J666) jumper pin 1 to pin 2 to disable
- (near J666) jumper pin 2 to pin 3 to enable
- For fixed Vout versions:
- omit R600 & C601 and insert 0.01uF cap in "R601" position
- R601: use 750k for 1.35 Vout
- vref dc/dc is 0.827V
- 1.8V 140mA for I/O from linear regulator
- 210mW max linear regulator dissipation
- (near R407) vref linear is 0.800V
- Variant
- 001
- Label Table
- Label Text
- ChangeMe!
- 002

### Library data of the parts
!PCB1 = PCB: Manufacturer: Any; PartNumber: PMP10411; SymbolCreator: a0412235
C300-C302 = GRM155R60J225ME15D: CAP, CERM, 2.2 µF, 6.3 V, +/- 20%, X5R, 0402; Manufacturer: MuRata; Polarized: N; CompType: Capacitor; Value: 2.2uF; U/M: EA; Cap_F: 0.0000022; Tolerance_%: 20; ESR_ohm: 0.005; Value1: 0.005 ohm; VDC_V: 6.3; Value2: 6.3V; IRMS_A: 3.67; TaMin_C: -55; TaMax_C: 125
C400 = GRM155R71H332KA01D: CAP, CERM, 3300 pF, 50 V, +/- 10%, X7R, 0402; Manufacturer: MuRata; Polarized: N; CompType: Capacitor; Value: 3300pF; U/M: EA; Cap_F: 0.0000000033; Tolerance_%: 10; Value1: Unknown; VDC_V: 50; Value2: 50V; TaMin_C: -55; TaMax_C: 125
C401 = GRM1555C1E470JA01D: CAP, CERM, 47pF, 25V, +/-5%, C0G/NP0, 0402; Manufacturer: MuRata; Polarized: N; CompType: Capacitor; U/M: EA; Cap_F: 0.000000000047; Tolerance_%: 5; Value1: Unknown; VDC_V: 25; TaMin_C: -55; TaMax_C: 125
C402 = GRM155R71H331KA01D: CAP, CERM, 330 pF, 50 V, +/- 10%, X7R, 0402; Manufacturer: MuRata; Polarized: N; CompType: Capacitor; Value: 330pF; U/M: EA; Cap_F: 0.00000000033; Tolerance_%: 10; Value1: Unknown; VDC_V: 50; Value2: 50V; TaMin_C: -55; TaMax_C: 125
C403 C410 = GRM155R71H103KA88D: CAP, CERM, 0.01 µF, 50 V, +/- 10%, X7R, 0402; Manufacturer: MuRata; Polarized: N; CompType: Capacitor; Value: 0.01uF; U/M: EA; Cap_F: 0.00000001; Tolerance_%: 10; Value1: Unknown; VDC_V: 50; Value2: 50V; TaMin_C: -55; TaMax_C: 125
C404 C413 C415 C614 = GRM155R61E104KA87D: as C1 on sheet PMP10411A_Main3v3&Boost&sequencing
C405-C408 C412 = GRM21BR61A226ME44: as C107 on sheet PMP10411A_Main3v3&Boost&sequencing
C409 = CGB3B1X5R1A475K055AC: CAP, CERM, 4.7uF, 10V, +/-10%, X5R, 0603; Manufacturer: TDK; Polarized: N; CompType: Capacitor; U/M: EA; Cap_F: 0.0000047; Tolerance_%: 10; Value1: Unknown; TaMin_C: -55; TaMax_C: 85
C414 C500 = GRM188R60J475ME19D: CAP, CERM, 4.7 µF, 6.3 V, +/- 20%, X5R, 0603; Manufacturer: MuRata; Polarized: N; CompType: Capacitor; Value: 4.7uF; U/M: EA; Cap_F: 0.0000047; Tolerance_%: 20; ESR_ohm: 0.001; Value1: 0.001 ohm; VDC_V: 6.3; Value2: 6.3V; TaMin_C: -55; TaMax_C: 125
C501 C600 C602 C610-C613 C615 = GRM188R60J106ME84: CAP, CERM, 10 µF, 6.3 V, +/- 20%, X5R, 0603; Manufacturer: MuRata; Polarized: N; CompType: Capacitor; Value: 10uF; U/M: EA; Cap_F: 0.00001; Tolerance_%: 20; Value1: Unknown; VDC_V: 6.3; Value2: 6.3V; TaMin_C: -55; TaMax_C: 85
C601 = GRM1555C1H220JA01D: CAP, CERM, 22 pF, 50 V, +/- 5%, C0G/NP0, 0402; Manufacturer: MuRata; Polarized: N; CompType: Capacitor; Value: 22pF; U/M: EA; Cap_F: 0.000000000022; Tolerance_%: 5; Value1: Unknown; VDC_V: 50; Value2: 50V; TaMin_C: -55; TaMax_C: 125
C616 = GRM155R61C102KA01D: CAP, CERM, 1000 pF, 16 V, +/- 10%, X5R, 0402; Manufacturer: MuRata; Polarized: N; CompType: Capacitor; Value: 1000pF; U/M: EA; Cap_F: 0.000000001; Tolerance_%: 10; Value1: Unknown; VDC_V: 16; Value2: 16V; TaMin_C: -55; TaMax_C: 85
FID1-FID3 = Fiducial: Fiducial mark.  There is nothing to buy or mount.; SymbolCreator: codlsc
H1-H4 = SJ-5303 (CLEAR): Bumpon, Hemisphere, 0.44 X 0.20, Clear; Manufacturer: 3M; SymbolCreator: a0412235
J300 J600 = ED555/3DS: Terminal Block, 6A, 3.5mm Pitch, 3-Pos, TH; Manufacturer: On-Shore Technology; SymbolCreator: a0799628; CompType: Connector; U/M: EA
J400 J401 J500 = ED555/2DS: as J100 on sheet PMP10411A_Main3v3&Boost&sequencing
J666 = PBC03SAAN: Header, 100mil, 3x1, Gold, TH; Manufacturer: Sullins Connector Solutions; Value: 1x3; U/M: EA
L400 = XAL4030-332MEB: Inductor, Shielded, Composite, 3.3uH, 5.5A, 0.026 ohm, SMD; Manufacturer: Coilcraft; Ind_H: 3.3E-6; ValueDisplayed: 3.3µH; Imax_A: 5.5; Irms: 6.6A @ 40C rise; Isat: 5.5A @ 30% inductance drop; DCR_ohm: 0.026; U/M: EA
L500 = LPS3015-222MLB: Inductor, Shielded Drum Core, Ferrite, 2.2 µH, 1.4 A, 0.11 ohm, SMD; Manufacturer: Coilcraft; Ind_H: 2.2E-6; ValueDisplayed: 2.2µH; Imax_A: 1.4; Irms: 1.4A @ 40C rise; Isat: 2.1A @ 30% inductance drop; DCR_ohm: 0.11; Value2: 1.4A
R400 = CRCW04022K80FKED: RES, 2.80 k, 1%, 0.063 W, 0402; Manufacturer: Vishay-Dale; CompType: Resistor; Value: 2.80k; Res_ohm: 2800; Value_Code: 2k80; Tolerance_%: 1; Power_W: 0.063; Value2: 0.063W; VDC_V: 50; TempCo: 100 ppm/C; EIA_Code: E96; U/M: EA
R401 = CRCW04027K68FKED: RES, 7.68k ohm, 1%, 0.063W, 0402; Manufacturer: Vishay-Dale; CompType: Resistor; Res_ohm: 7680; Value_Code: 7k68; Tolerance_%: 1; Power_W: 0.063; VDC_V: 50; TempCo: 100 ppm/C; EIA_Code: E96; U/M: EA
R402 R404 R405 R407 R610 R611 = CRCW040210K0FKED: as R8 on sheet PMP10411A_Main3v3&Boost&sequencing
R403 = CRCW040284K5FKED: RES, 84.5 k, 1%, 0.063 W, 0402; Manufacturer: Vishay-Dale; CompType: Resistor; Value: 84.5k; Res_ohm: 84500; Value_Code: 84k5; Tolerance_%: 1; Power_W: 0.063; Value2: 0.063W; VDC_V: 50; TempCo: 100 ppm/C; EIA_Code: E96; U/M: EA
R406 = CRCW040212K4FKED: RES, 12.4 k, 1%, 0.063 W, 0402; Manufacturer: Vishay-Dale; CompType: Resistor; Value: 12.4k; Res_ohm: 12400; Value_Code: 12k4; Tolerance_%: 1; Power_W: 0.063; Value2: 0.063W; VDC_V: 50; TempCo: 100 ppm/C; EIA_Code: E96; U/M: EA
R600 = CRCW0402100KFKED: as R1 on sheet PMP10411A_Main3v3&Boost&sequencing
R601 = CRCW0402392KFKED: RES, 392 k, 1%, 0.063 W, 0402; Manufacturer: Vishay-Dale; CompType: Resistor; Value: 392k; Res_ohm: 392000; Tolerance_%: 1; Power_W: 0.063; Value2: 0.063W; VDC_V: 50; TempCo: 100 ppm/C; EIA_Code: E96; U/M: EA
R666 = CRCW06030000Z0EA: RES, 0, 5%, 0.1 W, 0603; Manufacturer: Vishay-Dale; CompType: Resistor; Value: 0; Value_Code: 0000; Tolerance_%: 5; Power_W: 0.1; Value2: 0.1W; VDC_V: 75; TempCo: 200 ppm/C; EIA_Code: E24; U/M: EA
TP300 TP401 TP405 TP501 TP601 TP610 TP612 = 5000: as TP900 on sheet PMP10411A_CoverSheet
TP301 = 5004: Test Point, Miniature, Yellow, TH; Manufacturer: Keystone; CompType: Test Point Loop; U/M: EA
TP302 TP403 TP406 TP502 TP602 TP611 = 5001: as TP92 on sheet PMP10411A_Main3v3&Boost&sequencing
TP400 TP500 = 5015: as TP100 on sheet PMP10411A_Main3v3&Boost&sequencing
TP402 TP404 = 5002: as TP1 on sheet PMP10411A_Main3v3&Boost&sequencing
U300 = TPS22968QDMGTQ1: TPS22968QDMGTQ1, DMG0010A; Manufacturer: Texas Instruments; SymbolCreator: Altium; CompType: IC; U/M: EA
U400 = TPS54122RHL: Dual-Output, 3-A, Quiet Supply with Integrated DC-DC Converter and Low-Noise LDO, RHL0024A; Manufacturer: Texas Instruments; SymbolCreator: Altium; CompType: IC; U/M: EA
U500 = TPS62262DRVR: Buck Step Down Regulator with 2 to 6 V Input and 1.2 V Output, -40 to 85 degC, 6-Pin SON (DRV), Green (RoHS & no Sb/Br); Manufacturer: Texas Instruments; Alternate Manufacturer: None; Alternate PartNumber: Equivalent; Duty Cycle(Max)(%): 100; Iout(Max)(A): 0.6; Iq(Typ)(mA): 0.015; Preset Vout(V): 1.2; Rating: Catalog; Regulated Outputs(#): 1; SubFamily: Step-Down Regulator; Synchronous Rectification: TRUE; Vin(Max)(V): 6; Vin(Min)(V): 2
U600 = TPS79901QDRVRQ1: Single Output High PSRR LDO, 200 mA, Adjustable 1.2 to 6.5 V Output, 2.7 to 6.5 V Input, with Low IQ, 6-pin SON (DRV), -40 to 125 degC, Green (RoHS & no Sb/Br); Manufacturer: Texas Instruments; Alternate Manufacturer: None; Alternate PartNumber: Equivalent; Accuracy(%): 2; Iout(Max)(A): 0.2; Iq(Typ)(mA): 0.04; Rating: Automotive; SubFamily: Single Channel LDO; Vdo(Typ)(mV): 90; Vin(Max)(V): 6.5; Vin(Min)(V): 2.7; Vout Adj(Min)(V): 1.2
U610 = TPS51200QDRCRQ1: Single Output Automotive LDO, 3 A, 2.3 to 3.5 V Input, with DDR Termination, 10-pin SON (DRC), -40 to 125 degC, Green (RoHS & no Sb/Br); Manufacturer: Texas Instruments; Alternate Manufacturer: None; Alternate PartNumber: Equivalent; Iout(Max)(A): 3; Iq(Typ)(mA): 0.5; Power Good: TRUE; SubFamily: Single Channel LDO; Vin(Max)(V): 3.5; Vin(Min)(V): 2.3

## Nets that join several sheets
1v2: PMP10411A_CoverSheet (R905.2), PMP10411A_LowV_outputs (5 pins)
1v06: PMP10411A_CoverSheet (R904.2), PMP10411A_LowV_outputs (7 pins)
3v3: PMP10411A_CoverSheet (5 pins), PMP10411A_Main3v3&Boost&sequencing (26 pins), PMP10411A_LowV_outputs (20 pins)
5V: PMP10411A_CoverSheet (C904.1 U901.6), PMP10411A_Main3v3&Boost&sequencing (6 pins)
GND: PMP10411A_CoverSheet (12 pins), PMP10411A_Main3v3&Boost&sequencing (39 pins), PMP10411A_LowV_outputs (56 pins)
EN_2: PMP10411A_Main3v3&Boost&sequencing (R1.1 U1.6), PMP10411A_LowV_outputs (U400.12 U600.4)
EN_3: PMP10411A_Main3v3&Boost&sequencing (R2.1 U1.5), PMP10411A_LowV_outputs (U300.4)
EN_4: PMP10411A_Main3v3&Boost&sequencing (R3.1 U1.4 U4.2), PMP10411A_LowV_outputs (U500.4)
EN_5: PMP10411A_Main3v3&Boost&sequencing (R4.1 U2.2 U3.6), PMP10411A_LowV_outputs (U400.7)
EN_6: PMP10411A_Main3v3&Boost&sequencing (R5.1 U3.5), PMP10411A_LowV_outputs (U300.2)

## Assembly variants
001: not fitted FID1 FID2 FID3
